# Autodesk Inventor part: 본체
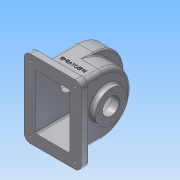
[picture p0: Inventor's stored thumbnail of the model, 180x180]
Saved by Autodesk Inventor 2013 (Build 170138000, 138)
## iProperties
Created: 2017-11
Part Number: 본체
Material: 알루미늄 6061
Document SubType Name: Modeling
Designer: Administrator
Density: 2.71 g/cm^3
Mass: 1079.49 g
Surface Area: 1182.07 cm^2
Volume: 398.334 cm^3
Author: Administrator
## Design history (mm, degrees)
sketch "스케치1"
  geometry: L1 (-80, 58)-(0, 58); L2 (0, 58)-(0, -58); L3 (0, -58)-(-80, -58); L4 (-80, -58)-(-80, 58); A1 r 58 centre (0, 0) between (0, -58) and (0, 58); A2 r 58 centre (-23, 0) between (-23, -58) and (-23, 58); 2 further points
  constraints: 8 end point, 4 point on circle, 3 coincident, 2 centre point, 2 parallel, 2 point on line, 1 horizontal, 1 horizontal alignment, 1 midpoint, 1 perpendicular
  dimensions: "d2" = 116 distance of L1.end L2.end; "d3" = 80 distance of L2.end L3.end; "d7" = 116 diameter of A2; "d8" = 57 distance from line of A2.centre L4
extrude "돌출1" new body sketch "스케치1" distance "d4" = 38; taper "d5" = 0 deg
extrude "돌출2" join sketch "스케치1" distance "d9" = 38; taper "d10" = 0 deg
feature "쉘1" dims "d15" = 5
sketch "스케치2"
  geometry: L1 (-17, 133)-(93, 133); L2 (93, 133)-(93, -17); L3 (93, -17)-(-17, -17); L4 (-17, -17)-(-17, 133); L5 (-17, 133)-(93, -17); L6 (93, 133)-(-17, -17); L7 (0, 116)-(76, 116) reference; L8 (0, 0)-(0, 116) reference; L9 (5, 111)-(71, 111) reference; L10 (71, 111)-(71, 5) reference; L11 (71, 5)-(5, 5) reference; L12 (5, 5)-(5, 111) reference; L13 (0, 116)-(76, 116) reference; L14 (0, 0)-(0, 116) reference; L15 (76, 0)-(0, 0) reference; L16 (76, 116)-(76, 0) reference; 1 further point
  constraints: 12 end point, 2 midpoint, 2 parallel, 1 horizontal, 1 perpendicular
  dimensions: "d11" = 110 distance of L2.end L3.end; "d12" = 150 distance of L1.end L2.end
extrude "돌출3" join sketch "스케치2" distance "d13" = 15; taper "d14" = 0 deg
sketch "스케치3"
  geometry: L1 (-75, -80)-(75, -80) reference; C1 r 37.5 at (0, -15); C2 r 16 at (0, -15); A1 r 58 centre (0, 0) between (58, 0) and (-58, 0) reference
  constraints: 2 centre point, 1 coincident, 1 vertical alignment
  dimensions: "d16" = 75 diameter of C1; "d17" = 32 diameter of C2; "d18" = 65 distance from line of C1.centre L1
extrude "돌출4" join sketch "스케치3" distance "d19" = 9; taper "d20" = 0 deg
extrude "돌출5" cut sketch "스케치3" stored distance "d21" = 0; taper "d22" = 0 deg
sketch "스케치4"
  geometry: C1 r 16 at (0, 0) reference; 5 further points
  constraints: 2 horizontal alignment, 2 vertical alignment
  dimensions: "d23" = 29 distance of point (0, 29) C1.centre; "d24" = 58 distance of point (0, -29) point (0, 29); "d25" = 58 distance of point (29, 0) point (-29, 0); "d26" = 29 distance of C1.centre point (29, 0)
hole "구멍1" sketch "스케치4" at (0, 29), (-29, 0), (0, -29), (29, 0) diameter "d27" = 2.459; stored, may be unused: countersink angle "d31" = 90 deg, drill point angle "d33" = 118 deg; dims "d28" = 6, "d29" = 4, "d30" = 2, "d32" = 8
sketch "스케치5"
  geometry: C1 r 16 at (0, -15) reference; C2 r 31 at (0, -15); 1 further point
  constraints: 1 centre point, 1 coincident
  dimensions: "d35" = 62 diameter of C2
extrude "돌출6" join sketch "스케치5" distance "d36" = 10; taper "d37" = 0 deg
sketch "스케치6" dims "d38" = 52
  geometry: C1 r 16 at (0, 0) reference; C2 r 31 at (0, 0) reference; 3 further points
  constraints: 2 vertical alignment, 1 coincident, 2 other
hole "구멍2" sketch "스케치6" at (0, 26) diameter "d39" = 2.459; stored, may be unused: countersink angle "d43" = 90 deg, drill point angle "d45" = 118 deg; dims "d40" = 6, "d41" = 4, "d42" = 2, "d44" = 8
fillet "모깎기1" dims "d49" = 12, "d50" = 8
fillet "모깎기2" dims "d51" = 3
node "작업 평면1"
sketch "스케치7"
  geometry: C1 r 6 at (19, 0); 1 further point
  constraints: 1 centre point, 1 horizontal alignment
  dimensions: "d52" = 12 diameter of C1; "d53" = 19 distance of point (0, 0) C1.centre
extrude "돌출7" join sketch "스케치7" distance "d54" = 6; taper "d56" = 0 deg; dims "d55" = 5, "d57" = 0
hole "구멍3" diameter "d60" = 4.459; stored, may be unused: countersink angle "d64" = 90 deg, drill point angle "d66" = 118 deg; dims "d58" = 10, "d59" = 10, "d61" = 6, "d62" = 4, "d63" = 2, "d65" = 8
fillet "모깎기3" dims "d67" = 3
fillet "모깎기4" dims "d68" = 3
sketch "스케치8"
  geometry: C1 r 6 at (-5, 5); C2 r 2.5 at (-5, 5); C3 r 6 at (81, 5); C4 r 2.5 at (81, 5); C5 r 6 at (81, -121); C6 r 2.5 at (81, -121); C7 r 6 at (-5, -121); C8 r 2.5 at (-5, -121); A1 r 9 centre (-5, 5) between (-5, 14) and (-14, 5) reference; A2 r 9 centre (-5, -121) between (-14, -121) and (-5, -130) reference; A3 r 9 centre (81, -121) between (81, -130) and (90, -121) reference; A4 r 9 centre (81, 5) between (90, 5) and (81, 14) reference; 1 further point
  constraints: 8 centre point, 8 coincident
  dimensions: "d69" = 12 diameter of C1; "d70" = 5 diameter of C2; "d71" = 12 diameter of C3; "d72" = 5 diameter of C4; "d73" = 12 diameter of C5; "d74" = 5 diameter of C6; "d75" = 12 diameter of C7; "d76" = 5 diameter of C8
extrude "돌출8" cut sketch "스케치8" distance "d77" = 5; taper "d78" = 0 deg
extrude "돌출9" cut sketch "스케치8" stored distance "d79" = 0; taper "d80" = 0 deg
sketch "스케치10"
  geometry: L1 (-13, -18)-(73, -18) reference; L2 (-8, 62)-(-8, 0) reference; 2 further points
  constraints: 1 other
  dimensions: "d85" = 40 distance from line of L1 point (30, 22); "d86" = 38 distance from line of L2 point (30, 22)
feature "엠보싱2" sketch "스케치10" dims "d2" = 116, "d3" = 80, "d7" = 116, "d8" = 57, "d87" = 0.5, "d88" = 0
chamfer "모따기1" distance "d89" = 1; stored, may be unused: second distance "d90" = 2, angle "d91" = 45 deg
node "솔리드1"
pattern_circular "원형 패턴1" dims angle "d47" = 360 deg
node "투영된 루프1"
